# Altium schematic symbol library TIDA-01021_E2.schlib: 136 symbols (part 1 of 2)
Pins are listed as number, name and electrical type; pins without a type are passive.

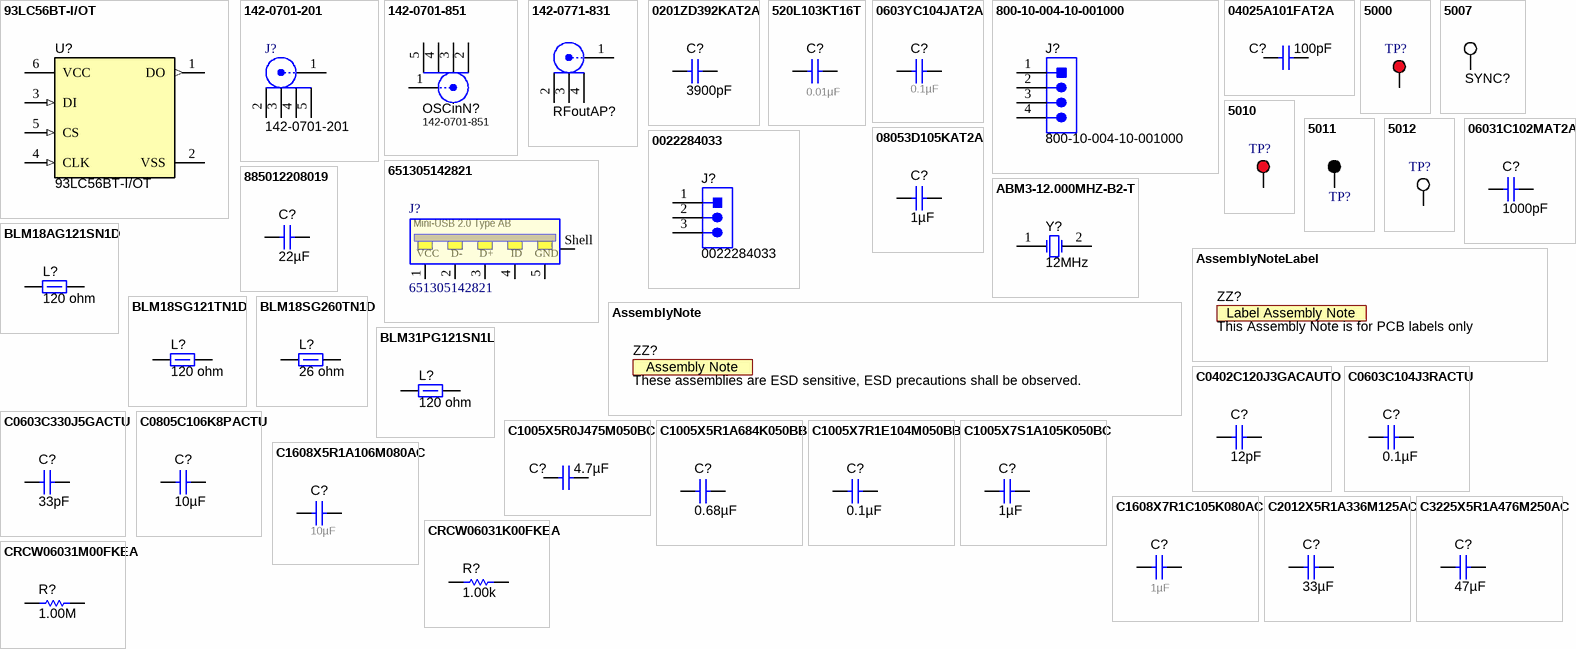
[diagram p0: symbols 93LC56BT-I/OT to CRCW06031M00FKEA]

## 93LC56BT-I/OT
designator U?
2K Microwire Compatible Serial EEPROM, SOT-23-6; Manufacturer: Microchip; SymbolCreator: x0208326; SizeAreaWB_mm2: 14.82; SizeArea_mm2: 8.12; SizeX_mm: 2.9; SizeY_mm: 2.8; SizeZ_mm: 1.15
footprint SOT-23-6
pins: 1 DO (out), 2 VSS (power), 3 DI (in), 4 CLK (in), 5 CS (in), 6 VCC (power)

## 142-0701-201
designator J?
Connector, TH, SMA; Manufacturer: Emerson Network Power; SymbolCreator: X0208326
footprint Johnson_142-0701-20x (Johnson Components recommended land pattern)
pins: 1, 2, 3, 4, 5

## 142-0701-851
designator OSCinN?
Connector, SMT, End launch SMA 50 ohm; Manufacturer: Emerson Network Power Connectivity; U/M: EA
footprint EMERSON_142-0701-851 (Johnson Components)
pins: 1, 2, 3, 4, 5

## 142-0771-831
designator RFoutAP?  (value not drawn)
JACK, SMA, 50 Ohm, Gold, Edge Mount; Manufacturer: Johnson; SymbolCreator: Altium; Gender: Female; Voltage_V: 170
footprint Johnson_142-0771-831
pins: 1, 2, 3, 4

## 0201ZD392KAT2A
designator C?  ValueDisplayed: 3900pF  (hidden comment: 0201ZD392KAT2A)
CAP, CERM, 3900 pF, 10 V, +/- 10%, X5R, 0201; Manufacturer: AVX; Polarized: N; CompType: Capacitor; Value: 3900pF; U/M: EA; Cap_F: 0.0000000039; Tolerance_%: 10; Value1: Unknown; Value2: 10V; TaMin_C: -55; TaMax_C: 85; Cap_Case: 0201; SizeArea_mm2: 0.18; SizeAreaWB_mm2: 2.08; SizeX_mm: 0.6; SizeY_mm: 0.3; SizeZ_mm: 0.26; AEC Category: Q200
signal-integrity model Cap
simulation model Cap
footprint 0201
footprint 0201M
footprint 0201L
footprint 0201_Silk
pins: 1, 2

## 520L103KT16T
designator C?  ValueDisplayed: 0.01µF  (hidden comment: 520L103KT16T)
CAP, CERM, 0.01 µF, 16 V, +/- 10%, X7R, 0402; Manufacturer: AT Ceramics; Polarized: N; CompType: Capacitor; Value: 0.01uF; U/M: EA; Cap_F: 0.00000001; Tolerance_%: 10; Value1: Unknown; VDC_V: 16; Value2: 16V; TaMin_C: -55; TaMax_C: 125; Cap_Case: 0402; AEC Category: Q200; SizeArea_mm2: 0.5; SizeAreaWB_mm2: 3; SizeX_mm: 1; SizeZ_mm: 0.65
signal-integrity model Cap
simulation model Cap
footprint 0402_065
footprint 0402_065M
footprint 0402_065L
footprint 0402_065S
pins: 1, 2

## 0603YC104JAT2A
designator C?  ValueDisplayed: 0.1µF  (hidden comment: 0603YC104JAT2A)
CAP, CERM, 0.1uF, 16V, +/-5%, X7R, 0603; Manufacturer: AVX; Cap_Case: 0603; ESR_Ohm: 0.039; Polarized: N; TaMax_C: 125; TaMin_C: -55; Tolerance_%: 5; VDC_V: 16; Cap_F: 0.0000001; CompType: Capacitor; Value1: 0.039 ohm; U/M: EA
signal-integrity model Cap
simulation model Cap
footprint 0603
footprint 0603M
footprint 0603L
footprint 0603_HV
pins: 1, 2

## 800-10-004-10-001000
designator J?
Header, 100mil, 4x1, TH; Manufacturer: Mill-Max; SymbolCreator: a0412235
footprint Mill-Max_800-10-004-10-001000
pins: 1, 2, 3, 4

## 04025A101FAT2A
designator C?  ValueDisplayed: 100pF  (hidden comment: 04025A101FAT2A)
CAP, CERM, 100 pF, 50 V, +/- 1%, C0G/NP0, 0402; Manufacturer: AVX; Polarized: N; CompType: Capacitor; Value: 100pF; U/M: EA; Cap_F: 0.0000000001; Tolerance_%: 1; Value1: Unknown; VDC_V: 50; Value2: 50V; TaMin_C: -55; TaMax_C: 125; Cap_Case: 0402; SizeArea_mm2: 0.5; SizeAreaWB_mm2: 3; SizeZ_mm: 0.6; AEC Category: Q200
signal-integrity model Cap
simulation model Cap
footprint 0402
footprint 0402M
footprint 0402L
footprint 0402S
pins: 1, 2

## 5000
designator TP?  (value not drawn)
Test Point, Miniature, Red, TH; Manufacturer: Keystone; CompType: Test Point Loop; ContactFinish: Silver
footprint Keystone5000
pins: 1

## 5007
designator SYNC?  (value not drawn)
Test Point, Compact, White, TH; Manufacturer: Keystone; CompType: Test Point Loop; U/M: EA
footprint Keystone5007
pins: 1

## 5010
designator TP?  (value not drawn)
Test Point, Multipurpose, Red, TH; Manufacturer: Keystone; CompType: Test Point Loop; ContactFinish: Silver
footprint Keystone5010
pins: 1

## 5011
designator TP?  (value not drawn)
Test Point, Multipurpose, Black, TH; Manufacturer: Keystone; CompType: Test Point Loop; ContactFinish: Silver
footprint Keystone5011
pins: 1

## 5012
designator TP?  (value not drawn)
Test Point, Multipurpose, White, TH; Manufacturer: Keystone; CompType: Test Point Loop; ContactFinish: Silver
footprint Keystone5012
pins: 1

## 06031C102MAT2A
designator C?  ValueDisplayed: 1000pF  (hidden comment: 06031C102MAT2A)
CAP, CERM, 1000 pF, 100 V, +/- 20%, X7R, 0603; Manufacturer: AVX; Polarized: N; CompType: Capacitor; Value: 1000pF; U/M: EA; Cap_F: 0.000000001; Tolerance_%: 20; ESR_ohm: 0.276; Value1: 0.276 ohm; VDC_V: 100; Value2: 100V; TaMin_C: -55; TaMax_C: 125; Cap_Case: 0603; SizeArea_mm2: 1.28; SizeAreaWB_mm2: 4.68; SizeX_mm: 1.6; SizeY_mm: 0.8; SizeZ_mm: 1; AEC Category: Q200
signal-integrity model Cap
simulation model Cap
footprint 0603
footprint 0603M
footprint 0603L
footprint 0603_HV
footprint 0603S
pins: 1, 2

## 08053D105KAT2A
designator C?  ValueDisplayed: 1µF  (hidden comment: 08053D105KAT2A)
CAP, CERM, 1 µF, 25 V, +/- 10%, X5R, 0805; Manufacturer: AVX; Polarized: N; CompType: Capacitor; Value: 1uF; U/M: EA; Cap_F: 0.000001; Tolerance_%: 10; ESR_ohm: 0.012; Value1: 0.012 ohm; VDC_V: 25; Value2: 25V; TaMin_C: -55; TaMax_C: 85; Cap_Case: 0805; SizeArea_mm2: 2.5; SizeAreaWB_mm2: 6.75; SizeX_mm: 2; SizeY_mm: 1.25; SizeZ_mm: 1.45; AEC Category: Q200
signal-integrity model Cap
simulation model Cap
footprint 0805_HV
footprint 0805_HV1
footprint 0805
footprint 0805M
footprint 0805L
pins: 1, 2

## 0022284033
designator J?
Header, 2.54mm, 3x1, Tin, TH; Manufacturer: Molex; SymbolCreator: a0799628; Pitch_mm: 2.54; Gender: Male; Shrouded: N; Row_Count: 1; Current_A: 4; Voltage_V: 250; Cert_UL: Y
footprint Molex_0022284033
pins: 1, 2, 3
3 alternate drawings of the same symbol

## 651305142821
designator J?
WR-COM Mini USB 2.0 Type AB SMT Horizontal 5 Contacts
footprint 651305142821 (5 pins)
pins: 1 VCC, 2 D-, 3 D+, 4 ID, 5 GND, Shell

## 885012208019
designator C?  ValueDisplayed: 22µF  (hidden comment: 885012208019)
CAP, CERM, 22 µF, 10 V, +/- 10%, X7R, 1206_190; Manufacturer: Wurth Elektronik; Polarized: N; CompType: Capacitor; Value: 22uF; U/M: EA; Cap_F: 0.000022; Tolerance_%: 10; Value1: Unknown; Value2: 10V; TaMin_C: -55; TaMax_C: 125; Cap_Case: 1206; SizeArea_mm2: 5.12; SizeAreaWB_mm2: 10.92; SizeX_mm: 3.2; SizeY_mm: 1.6; SizeZ_mm: 1.9; AEC Category: Q200
signal-integrity model Cap
simulation model Cap
footprint 1206_190
footprint 1206_190M
footprint 1206_190L
pins: 1, 2

## ABM3-12.000MHZ-B2-T
designator Y?  Frequency: 12MHz  (hidden comment: ABM3-12.000MHZ-B2-T)
Crystal, 12Mhz, 18pF, SMD; Manufacturer: Abracon Corporation; SymbolCreator: a0412235; U/M: EA; TaMin_C: -20; TaMax_C: 70; Frequency Stability: ±50ppm
footprint XTAL_ABM3
pins: 1 OSC1, 2 OSC2

## AssemblyNote
designator ZZ?, comment These assemblies are ESD sensitive, ESD precautions shall be observed.  (no BOM)
SymbolCreator: codlsc; CompType: AssemblyNote
footprint AssemblyNote

## AssemblyNoteLabel
designator ZZ?, comment This Assembly Note is for PCB labels only  (no BOM)
SymbolCreator: a0412235
footprint AssemblyNoteLabel

## BLM18AG121SN1D
designator L?  ValueDisplayed: 120 ohm  (hidden comment: BLM18AG121SN1D)
Ferrite Bead, 120 ohm @ 100 MHz, 0.5 A, 0603; Manufacturer: MuRata; Value: 120 ohm; Imax_A: 0.5; DCR_ohm: 0.18; Value1: 0.18 ohm; Value2: 0.5A; SizeAreaWB_mm2: 4.68; SizeArea_mm2: 1.28; SizeX_mm: 1.6; SizeY_mm: 0.8; SizeZ_mm: 1; ZTyp@100MHz_Ohm: 120
footprint 0603
footprint 0603M
footprint 0603L
footprint 0603_HV
footprint 0603S
pins: 1, 2

## BLM18SG121TN1D
designator L?  ValueDisplayed: 120 ohm  (hidden comment: BLM18SG121TN1D)
Ferrite Bead, 120 ohm @ 100 MHz, 3 A, 0603; Manufacturer: MuRata; Value: 120 ohm; Imax_A: 3; DCR_ohm: 0.025; Value1: 0.025 ohm; Value2: 3A; SizeAreaWB_mm2: 4.68; SizeArea_mm2: 1.28; SizeX_mm: 1.6; SizeY_mm: 0.8; SizeZ_mm: 1; ZTyp@100MHz_Ohm: 120
footprint 0603
footprint 0603M
footprint 0603L
footprint 0603_HV
footprint 0603S
pins: 1, 2

## BLM18SG260TN1D
designator L?  ValueDisplayed: 26 ohm  (hidden comment: BLM18SG260TN1D)
Ferrite Bead, 26 ohm @ 100 MHz, 6 A, 0603; Manufacturer: MuRata; Value: 26 ohm; Imax_A: 6; DCR_ohm: 0.007; Value1: 0.007 ohm; Value2: 6A; SizeAreaWB_mm2: 4.68; SizeArea_mm2: 1.28; SizeX_mm: 1.6; SizeY_mm: 0.8; SizeZ_mm: 1; ZTyp@100MHz_Ohm: 26
footprint 0603
footprint 0603M
footprint 0603L
footprint 0603_HV
footprint 0603S
pins: 1, 2

## BLM31PG121SN1L
designator L?  ValueDisplayed: 120 ohm  (hidden comment: BLM31PG121SN1L)
Ferrite Bead, 120 ohm @ 100 MHz, 3.5 A, 1206; Manufacturer: MuRata; Value: 120 ohm; Imax_A: 3.5; DCR_ohm: 0.02; Value1: 0.02 ohm; Value2: 3.5A; SizeAreaWB_mm2: 10.92; SizeArea_mm2: 5.12; SizeX_mm: 3.2; SizeY_mm: 1.6; SizeZ_mm: 1.35; ZTyp@100MHz_Ohm: 120
footprint 1206
footprint 1206M
footprint 1206L
pins: 1, 2

## C0402C120J3GACAUTO
designator C?  ValueDisplayed: 12pF  (hidden comment: C0402C120J3GACAUTO)
CAP, CERM, 12 pF, 25 V, +/- 5%, C0G/NP0, AEC-Q200 Grade 1, 0402; Manufacturer: Kemet; Polarized: N; CompType: Capacitor; Value: 12pF; U/M: EA; Cap_F: 0.000000000012; Tolerance_%: 5; Value1: Unknown; VDC_V: 25; Value2: 25V; TaMin_C: -55; TaMax_C: 125; Cap_Case: 0402; SizeArea_mm2: 0.5; SizeAreaWB_mm2: 3; SizeX_mm: 1; SizeZ_mm: 0.6; AEC Category: Q200; AEC Qualified: Y
signal-integrity model Cap
simulation model Cap
footprint 0402
footprint 0402M
footprint 0402L
footprint 0402S
pins: 1, 2

## C0603C104J3RACTU
designator C?  ValueDisplayed: 0.1µF  (hidden comment: C0603C104J3RACTU)
CAP, CERM, 0.1uF, 25V, +/-5%, X7R, 0603; Manufacturer: Kemet; Cap_Case: 0603; Polarized: N; TaMax_C: 125; TaMin_C: -55; Tolerance_%: 5; VDC_V: 25; Cap_F: 0.0000001; CompType: Capacitor; Value1: Unknown; U/M: EA
signal-integrity model Cap
simulation model Cap
footprint 0603
footprint 0603M
footprint 0603L
footprint 0603_HV
pins: 1, 2

## C0603C330J5GACTU
designator C?  ValueDisplayed: 33pF  (hidden comment: C0603C330J5GACTU)
CAP, CERM, 33pF, 50V, +/-5%, C0G/NP0, 0603; Manufacturer: Kemet; Cap_Case: 0603; Polarized: N; TaMax_C: 125; TaMin_C: -55; Tolerance_%: 5; VDC_V: 50; Cap_F: 0.000000000033; CompType: Capacitor; U/M: EA; Value1: Unknown
signal-integrity model Cap
simulation model Cap
footprint 0603
footprint 0603M
footprint 0603L
footprint 0603_HV
pins: 1, 2

## C0805C106K8PACTU
designator C?  ValueDisplayed: 10µF  (hidden comment: C0805C106K8PACTU)
CAP, CERM, 10uF, 10V, +/-10%, X5R, 0805; Manufacturer: Kemet; Cap_Case: 0805; ESR_Ohm: 0.003; IRMS_A: 11.43; Polarized: N; TaMax_C: 85; TaMin_C: -55; Tolerance_%: 10; Cap_F: 0.00001; CompType: Capacitor; Value1: 0.003 ohm; U/M: EA
signal-integrity model Cap
simulation model Cap
footprint 0805_HV
footprint 0805
footprint 0805M
footprint 0805L
pins: 1, 2

## C1005X5R0J475M050BC
designator C?  ValueDisplayed: 4.7µF  (hidden comment: C1005X5R0J475M050BC)
CAP, CERM, 4.7 µF, 6.3 V, +/- 20%, X5R, 0402; Manufacturer: TDK; Polarized: N; CompType: Capacitor; Value: 4.7uF; U/M: EA; Cap_F: 0.0000047; Tolerance_%: 20; Value1: Unknown; VDC_V: 6.3; Value2: 6.3V; TaMin_C: -55; TaMax_C: 85; Cap_Case: 0402; SizeArea_mm2: 0.5; SizeAreaWB_mm2: 3; SizeX_mm: 1; SizeZ_mm: 0.6; AEC Category: Q200
signal-integrity model Cap
simulation model Cap
footprint 0402
footprint 0402M
footprint 0402L
footprint 0402S
pins: 1, 2

## C1005X5R1A684K050BB
designator C?  ValueDisplayed: 0.68µF  (hidden comment: C1005X5R1A684K050BB)
CAP, CERM, 0.68 µF, 10 V, +/- 10%, X5R, 0402; Manufacturer: TDK; Polarized: N; CompType: Capacitor; Value: 0.68uF; U/M: EA; Cap_F: 0.00000068; Tolerance_%: 10; Value1: Unknown; Value2: 10V; TaMin_C: -55; TaMax_C: 85; Cap_Case: 0402; SizeArea_mm2: 0.5; SizeAreaWB_mm2: 3; SizeX_mm: 1; SizeZ_mm: 0.6; AEC Category: Q200
signal-integrity model Cap
simulation model Cap
footprint 0402
footprint 0402M
footprint 0402L
footprint 0402S
pins: 1, 2

## C1005X7R1E104M050BB
designator C?  ValueDisplayed: 0.1µF  (hidden comment: C1005X7R1E104M050BB)
CAP, CERM, 0.1 µF, 25 V, +/- 20%, X7R, 0402; Manufacturer: TDK; Cap_Case: 0402; Polarized: N; TaMax_C: 125; TaMin_C: -55; Tolerance_%: 20; VDC_V: 25; Cap_F: 0.0000001; CompType: Capacitor; Value: 0.1uF; Value1: Unknown; Value2: 25V; U/M: EA; SizeArea_mm2: 0.5; SizeAreaWB_mm2: 3; SizeX_mm: 1; SizeZ_mm: 0.6; AEC Category: Q200
signal-integrity model Cap
simulation model Cap
footprint 0402
footprint 0402M
footprint 0402L
footprint 0402S
pins: 1, 2

## C1005X7S1A105K050BC
designator C?  ValueDisplayed: 1µF  (hidden comment: C1005X7S1A105K050BC)
CAP, CERM, 1 µF, 10 V, +/- 10%, X7S, 0402; Manufacturer: TDK; Polarized: N; CompType: Capacitor; Value: 1uF; U/M: EA; Cap_F: 0.000001; Tolerance_%: 10; ESR_ohm: 0.011416; Value1: 0.011416 ohm; Value2: 10V; IRMS_A: 1.483; TaMin_C: -55; TaMax_C: 125; Cap_Case: 0402; SizeArea_mm2: 0.5; SizeAreaWB_mm2: 3; SizeX_mm: 1; SizeZ_mm: 0.6; AEC Category: Q200
signal-integrity model Cap
simulation model Cap
footprint 0402
footprint 0402M
footprint 0402L
footprint 0402S
pins: 1, 2

## C1608X5R1A106M080AC
designator C?  ValueDisplayed: 10µF  (hidden comment: C1608X5R1A106M080AC)
CAP, CERM, 10 µF, 10 V, +/- 20%, X5R, 0603; Manufacturer: TDK; Cap_Case: 0603; ESR_ohm: 0.0078; IRMS_A: 1.85; Polarized: N; TaMax_C: 85; TaMin_C: -55; Tolerance_%: 20; VDC_V: 10; Cap_F: 0.00001; CompType: Capacitor; Value: 10uF; U/M: EA; Value1: 0.0078 ohm; Value2: 10V; AEC Category: Q200
signal-integrity model Cap
simulation model Cap
footprint 0603
footprint 0603M
footprint 0603L
footprint 0603_HV
footprint 0603S
pins: 1, 2

## C1608X7R1C105K080AC
designator C?  ValueDisplayed: 1µF  (hidden comment: C1608X7R1C105K080AC)
CAP, CERM, 1 µF, 16 V, +/- 10%, X7R, 0603; Manufacturer: TDK; Cap_Case: 0603; ESR_ohm: 0.0057; Polarized: N; TaMax_C: 125; TaMin_C: -55; Tolerance_%: 10; VDC_V: 16; Cap_F: 0.000001; CompType: Capacitor; Value: 1uF; Value1: 0.0057 ohm; Value2: 16V; U/M: EA; SizeArea_mm2: 1.28; SizeAreaWB_mm2: 4.68; SizeX_mm: 1.6; SizeY_mm: 0.8; SizeZ_mm: 1; AEC Category: Q200
signal-integrity model Cap
simulation model Cap
footprint 0603
footprint 0603M
footprint 0603L
footprint 0603_HV
footprint 0603S
pins: 1, 2

## C2012X5R1A336M125AC
designator C?  ValueDisplayed: 33µF  (hidden comment: C2012X5R1A336M125AC)
CAP, CERM, 33 µF, 10 V, +/- 20%, X5R, 0805; Manufacturer: TDK; Polarized: N; CompType: Capacitor; Value: 33uF; U/M: EA; Cap_F: 0.000033; Tolerance_%: 20; ESR_ohm: 0.001694; Value1: 0.001694 ohm; VDC_V: 10; Value2: 10V; IRMS_A: 5.01281; TaMin_C: -55; TaMax_C: 85; Cap_Case: 0805; SizeArea_mm2: 2.5; SizeAreaWB_mm2: 6.75; SizeX_mm: 2; SizeY_mm: 1.25; SizeZ_mm: 1.45; AEC Category: Q200
signal-integrity model Cap
simulation model Cap
footprint 0805_HV
footprint 0805_HV1
footprint 0805
footprint 0805M
footprint 0805L
pins: 1, 2

## C3225X5R1A476M250AC
designator C?  ValueDisplayed: 47µF  (hidden comment: C3225X5R1A476M250AC)
CAP, CERM, 47 µF, 10 V, +/- 20%, X5R, 1210; Manufacturer: TDK; Polarized: N; CompType: Capacitor; Value: 47uF; U/M: EA; Cap_F: 0.000047; Tolerance_%: 20; ESR_ohm: 0.003602; Value1: 0.003602 ohm; VDC_V: 10; Value2: 10V; IRMS_A: 3.87414; TaMin_C: -55; TaMax_C: 85; Cap_Case: 1210_280; SizeArea_mm2: 8; SizeAreaWB_mm2: 14.7; SizeX_mm: 3.2; SizeY_mm: 2.5; SizeZ_mm: 2.8; AEC Category: Q200
signal-integrity model Cap
simulation model Cap
footprint 1210_280
pins: 1, 2

## CRCW06031K00FKEA
designator R?  ValueDisplayed: 1.00k  (hidden comment: CRCW06031K00FKEA)
RES, 1.00 k, 1%, 0.1 W, 0603; Manufacturer: Vishay-Dale; CompType: Resistor; Value: 1.00k; Res_ohm: 1000; Value_Code: 1k00; Tolerance_%: 1; Power_W: 0.1; Value2: 0.1W; VDC_V: 75; TempCo: 100 ppm/C; SizeArea_mm2: 1.28; SizeX_mm: 1.6; SizeY_mm: 0.8; EIA_Code: E96; U/M: EA; AEC Category: Q200
signal-integrity model Resistor
simulation model Resistor
footprint 0603
footprint 0603M
footprint 0603L
footprint 0603_HV
footprint 0603S
pins: 1, 2

## CRCW06031M00FKEA
designator R?  ValueDisplayed: 1.00M  (hidden comment: CRCW06031M00FKEA)
RES, 1.00 M, 1%, 0.1 W, 0603; Manufacturer: Vishay-Dale; CompType: Resistor; Value: 1.00Meg; Res_ohm: 1000000; Value_Code: 1M00; Tolerance_%: 1; Power_W: 0.1; Value2: 0.1W; VDC_V: 75; TempCo: 100 ppm/C; SizeArea_mm2: 1.28; SizeX_mm: 1.6; SizeY_mm: 0.8; EIA_Code: E96; U/M: EA; AEC Category: Q200
signal-integrity model Resistor
simulation model Resistor
footprint 0603
footprint 0603M
footprint 0603L
footprint 0603_HV
footprint 0603S
pins: 1, 2

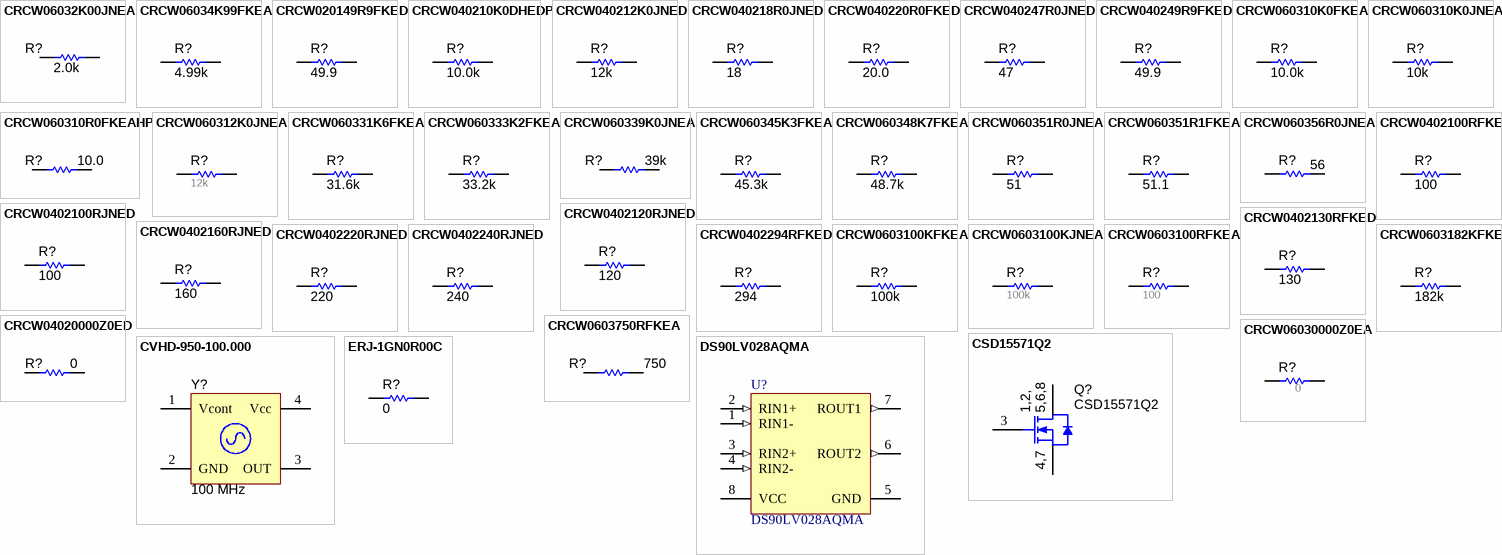
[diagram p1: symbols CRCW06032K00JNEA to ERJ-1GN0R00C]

## CRCW06032K00JNEA
designator R?  ValueDisplayed: 2.0k  (hidden comment: CRCW06032K00JNEA)
RES, 2.0 k, 5%, 0.1 W, 0603; Manufacturer: Vishay-Dale; CompType: Resistor; Value: 2.0k; Res_ohm: 2000; Value_Code: 2k00; Tolerance_%: 5; Power_W: 0.1; Value2: 0.1W; VDC_V: 75; TempCo: 200 ppm/C; SizeArea_mm2: 1.28; SizeX_mm: 1.6; SizeY_mm: 0.8; SizeZ_mm: 1; EIA_Code: E24; U/M: EA; AEC Category: Q200
signal-integrity model Resistor
simulation model Resistor
footprint 0603
footprint 0603M
footprint 0603L
footprint 0603_HV
footprint 0603S
pins: 1, 2

## CRCW06034K99FKEA
designator R?  ValueDisplayed: 4.99k  (hidden comment: CRCW06034K99FKEA)
RES, 4.99 k, 1%, 0.1 W, 0603; Manufacturer: Vishay-Dale; CompType: Resistor; Value: 4.99k; Res_ohm: 4990; Value_Code: 4k99; Tolerance_%: 1; Power_W: 0.1; Value2: 0.1W; VDC_V: 75; TempCo: 100 ppm/C; SizeArea_mm2: 1.28; SizeX_mm: 1.6; SizeY_mm: 0.8; EIA_Code: E96; U/M: EA; AEC Category: Q200
signal-integrity model Resistor
simulation model Resistor
footprint 0603
footprint 0603M
footprint 0603L
footprint 0603_HV
footprint 0603S
pins: 1, 2

## CRCW020149R9FKED
designator R?  ValueDisplayed: 49.9  (hidden comment: CRCW020149R9FKED)
RES, 49.9, 1%, 0.05 W, 0201; Manufacturer: Vishay-Dale; CompType: Resistor; Value: 49.9; Value_Code: 49R9; Tolerance_%: 1; Power_W: 0.05; Value2: 0.05W; VDC_V: 30; TempCo: 100 ppm/C; SizeArea_mm2: 0.18; SizeX_mm: 0.6; SizeY_mm: 0.3; SizeZ_mm: 0.26; EIA_Code: E96; U/M: EA; AEC Category: Q200; AEC Qualified: N
signal-integrity model Resistor
simulation model Resistor
footprint 0201
footprint 0201M
footprint 0201L
footprint 0201_Silk
pins: 1, 2

## CRCW040210K0DHEDP
designator R?  ValueDisplayed: 10.0k  (hidden comment: CRCW040210K0DHEDP)
RES, 10.0 k, 0.5%, 0.063 W, 0402; Manufacturer: Vishay-Dale; CompType: Resistor; Value: 10.0k; Res_ohm: 10000; Value_Code: 10k0; Tolerance_%: 0.5; Power_W: 0.063; Value2: 0.063W; VDC_V: 50; TempCo: 50 ppm/C; SizeX_mm: 1; SizeZ_mm: 0.6; EIA_Code: E192; U/M: EA; AEC Category: Q200
signal-integrity model Resistor
simulation model Resistor
footprint 0402
footprint 0402M
footprint 0402L
footprint 0402S
pins: 1, 2

## CRCW040212K0JNED
designator R?  ValueDisplayed: 12k  (hidden comment: CRCW040212K0JNED)
RES, 12 k, 5%, 0.063 W, 0402; Manufacturer: Vishay-Dale; CompType: Resistor; Value: 12k; Res_ohm: 12000; Value_Code: 12k0; Tolerance_%: 5; Power_W: 0.063; Value2: 0.063W; VDC_V: 50; TempCo: 200 ppm/C; EIA_Code: E24; U/M: EA; AEC Category: Q200
signal-integrity model Resistor
simulation model Resistor
footprint 0402
footprint 0402M
footprint 0402L
footprint 0402S
pins: 1, 2

## CRCW040218R0JNED
designator R?  ValueDisplayed: 18  (hidden comment: CRCW040218R0JNED)
RES, 18, 5%, 0.063 W, 0402; Manufacturer: Vishay-Dale; CompType: Resistor; Value: 18; Value_Code: 18R0; Tolerance_%: 5; Power_W: 0.063; Value2: 0.063W; VDC_V: 50; TempCo: 200 ppm/C; EIA_Code: E24; U/M: EA; AEC Category: Q200
signal-integrity model Resistor
simulation model Resistor
footprint 0402
footprint 0402M
footprint 0402L
footprint 0402S
pins: 1, 2

## CRCW040220R0FKED
designator R?  ValueDisplayed: 20.0  (hidden comment: CRCW040220R0FKED)
RES, 20.0, 1%, 0.063 W, 0402; Manufacturer: Vishay-Dale; CompType: Resistor; Value: 20.0; Res_ohm: 20; Value_Code: 20R0; Tolerance_%: 1; Power_W: 0.063; Value2: 0.063W; VDC_V: 50; TempCo: 100 ppm/C; SizeArea_mm2: 0.5; SizeZ_mm: 0.6; EIA_Code: E96; U/M: EA; AEC Category: Q200
signal-integrity model Resistor
simulation model Resistor
footprint 0402
footprint 0402M
footprint 0402L
footprint 0402S
pins: 1, 2

## CRCW040247R0JNED
designator R?  ValueDisplayed: 47  (hidden comment: CRCW040247R0JNED)
RES, 47, 5%, 0.063 W, 0402; Manufacturer: Vishay-Dale; CompType: Resistor; Value: 47; Value_Code: 47R0; Tolerance_%: 5; Power_W: 0.063; Value2: 0.063W; VDC_V: 50; TempCo: 200 ppm/C; SizeArea_mm2: 0.5; SizeX_mm: 1; SizeZ_mm: 0.6; EIA_Code: E24; U/M: EA; AEC Category: Q200
signal-integrity model Resistor
simulation model Resistor
footprint 0402
footprint 0402M
footprint 0402L
footprint 0402S
pins: 1, 2

## CRCW040249R9FKED
designator R?  ValueDisplayed: 49.9  (hidden comment: CRCW040249R9FKED)
RES, 49.9, 1%, 0.063 W, 0402; Manufacturer: Vishay-Dale; CompType: Resistor; Value: 49.9; Value_Code: 49R9; Tolerance_%: 1; Power_W: 0.063; Value2: 0.063W; VDC_V: 50; TempCo: 100 ppm/C; EIA_Code: E96; U/M: EA; AEC Category: Q200
signal-integrity model Resistor
simulation model Resistor
footprint 0402
footprint 0402M
footprint 0402L
footprint 0402S
pins: 1, 2

## CRCW060310K0FKEA
designator R?  ValueDisplayed: 10.0k  (hidden comment: CRCW060310K0FKEA)
RES, 10.0 k, 1%, 0.1 W, 0603; Manufacturer: Vishay-Dale; CompType: Resistor; Value: 10.0k; Res_ohm: 10000; Value_Code: 10k0; Tolerance_%: 1; Power_W: 0.1; Value2: 0.1W; VDC_V: 75; TempCo: 100 ppm/C; SizeArea_mm2: 1.28; SizeX_mm: 1.6; SizeY_mm: 0.8; EIA_Code: E96; U/M: EA; AEC Category: Q200
signal-integrity model Resistor
simulation model Resistor
footprint 0603
footprint 0603M
footprint 0603L
footprint 0603_HV
footprint 0603S
pins: 1, 2

## CRCW060310K0JNEA
designator R?  ValueDisplayed: 10k  (hidden comment: CRCW060310K0JNEA)
RES, 10 k, 5%, 0.1 W, 0603; Manufacturer: Vishay-Dale; CompType: Resistor; Value: 10k; Res_ohm: 10000; Value_Code: 10k0; Tolerance_%: 5; Power_W: 0.1; Value2: 0.1W; VDC_V: 75; TempCo: 200 ppm/C; SizeArea_mm2: 1.28; SizeX_mm: 1.6; SizeY_mm: 0.8; SizeZ_mm: 1; EIA_Code: E24; U/M: EA; AEC Category: Q200
signal-integrity model Resistor
simulation model Resistor
footprint 0603
footprint 0603M
footprint 0603L
footprint 0603_HV
footprint 0603S
pins: 1, 2

## CRCW060310R0FKEAHP
designator R?  ValueDisplayed: 10.0  (hidden comment: CRCW060310R0FKEAHP)
RES, 10.0, 1%, 0.25 W, 0603; Manufacturer: Vishay-Dale; CompType: Resistor; Value: 10.0; Res_ohm: 10; Value_Code: 10R0; Tolerance_%: 1; Power_W: 0.25; Value2: 0.25W; VDC_V: 75; TempCo: 100 ppm/C; SizeArea_mm2: 1.28; SizeX_mm: 1.6; SizeY_mm: 0.8; EIA_Code: E96; U/M: EA; AEC Category: Q200
signal-integrity model Resistor
simulation model Resistor
footprint 0603
footprint 0603M
footprint 0603L
footprint 0603_HV
footprint 0603S
pins: 1, 2

## CRCW060312K0JNEA
designator R?  value 12k  (hidden comment: CRCW060312K0JNEA)
RES, 12k ohm, 5%, 0.1W, 0603; Manufacturer: Vishay-Dale; CompType: Resistor; Tolerance_%: 5; VDC_V: 75; Power_W: 0.1; Res_ohm: 12000; U/M: EA; Value_Code: 12k0; EIA_Code: E24
signal-integrity model Resistor
simulation model Resistor
footprint 0603
footprint 0603M
footprint 0603L
footprint 0603_HV
pins: 1, 2

## CRCW060331K6FKEA
designator R?  ValueDisplayed: 31.6k  (hidden comment: CRCW060331K6FKEA)
RES, 31.6 k, 1%, 0.1 W, 0603; Manufacturer: Vishay-Dale; CompType: Resistor; Value: 31.6k; Res_ohm: 31600; Value_Code: 31k6; Tolerance_%: 1; Power_W: 0.1; Value2: 0.1W; VDC_V: 75; TempCo: 100 ppm/C; SizeArea_mm2: 1.28; SizeX_mm: 1.6; SizeY_mm: 0.8; EIA_Code: E96; U/M: EA; AEC Category: Q200
signal-integrity model Resistor
simulation model Resistor
footprint 0603
footprint 0603M
footprint 0603L
footprint 0603_HV
footprint 0603S
pins: 1, 2

## CRCW060333K2FKEA
designator R?  ValueDisplayed: 33.2k  (hidden comment: CRCW060333K2FKEA)
RES, 33.2 k, 1%, 0.1 W, 0603; Manufacturer: Vishay-Dale; CompType: Resistor; Value: 33.2k; Res_ohm: 33200; Value_Code: 33k2; Tolerance_%: 1; Power_W: 0.1; Value2: 0.1W; VDC_V: 75; TempCo: 100 ppm/C; SizeArea_mm2: 1.28; SizeX_mm: 1.6; SizeY_mm: 0.8; EIA_Code: E96; U/M: EA; AEC Category: Q200
signal-integrity model Resistor
simulation model Resistor
footprint 0603
footprint 0603M
footprint 0603L
footprint 0603_HV
footprint 0603S
pins: 1, 2

## CRCW060339K0JNEA
designator R?  ValueDisplayed: 39k  (hidden comment: CRCW060339K0JNEA)
RES, 39 k, 5%, 0.1 W, 0603; Manufacturer: Vishay-Dale; CompType: Resistor; Value: 39k; Res_ohm: 39000; Value_Code: 39k0; Tolerance_%: 5; Power_W: 0.1; Value2: 0.1W; VDC_V: 75; TempCo: 200 ppm/C; SizeArea_mm2: 1.28; SizeX_mm: 1.6; SizeY_mm: 0.8; SizeZ_mm: 1; EIA_Code: E24; U/M: EA; AEC Category: Q200
signal-integrity model Resistor
simulation model Resistor
footprint 0603
footprint 0603M
footprint 0603L
footprint 0603_HV
footprint 0603S
pins: 1, 2

## CRCW060345K3FKEA
designator R?  ValueDisplayed: 45.3k  (hidden comment: CRCW060345K3FKEA)
RES, 45.3 k, 1%, 0.1 W, 0603; Manufacturer: Vishay-Dale; CompType: Resistor; Value: 45.3k; Res_ohm: 45300; Value_Code: 45k3; Tolerance_%: 1; Power_W: 0.1; Value2: 0.1W; VDC_V: 75; TempCo: 100 ppm/C; SizeArea_mm2: 1.28; SizeX_mm: 1.6; SizeY_mm: 0.8; EIA_Code: E96; U/M: EA; AEC Category: Q200
signal-integrity model Resistor
simulation model Resistor
footprint 0603
footprint 0603M
footprint 0603L
footprint 0603_HV
footprint 0603S
pins: 1, 2

## CRCW060348K7FKEA
designator R?  ValueDisplayed: 48.7k  (hidden comment: CRCW060348K7FKEA)
RES, 48.7 k, 1%, 0.1 W, 0603; Manufacturer: Vishay-Dale; CompType: Resistor; Value: 48.7k; Res_ohm: 48700; Value_Code: 48k7; Tolerance_%: 1; Power_W: 0.1; Value2: 0.1W; VDC_V: 75; TempCo: 100 ppm/C; SizeArea_mm2: 1.28; SizeX_mm: 1.6; SizeY_mm: 0.8; EIA_Code: E96; U/M: EA; AEC Category: Q200
signal-integrity model Resistor
simulation model Resistor
footprint 0603
footprint 0603M
footprint 0603L
footprint 0603_HV
footprint 0603S
pins: 1, 2

## CRCW060351R0JNEA
designator R?  value 51  (hidden comment: CRCW060351R0JNEA)
RES, 51 ohm, 5%, 0.1W, 0603; Manufacturer: Vishay-Dale; CompType: Resistor; Tolerance_%: 5; VDC_V: 75; Power_W: 0.1; Value_Code: 51R0; EIA_Code: E24; TempCo: 200 ppm/C; U/M: EA
signal-integrity model Resistor
simulation model Resistor
footprint 0603
footprint 0603M
footprint 0603L
footprint 0603_HV
pins: 1, 2

## CRCW060351R1FKEA
designator R?  ValueDisplayed: 51.1  (hidden comment: CRCW060351R1FKEA)
RES, 51.1, 1%, 0.1 W, 0603; Manufacturer: Vishay-Dale; CompType: Resistor; Value: 51.1; Value_Code: 51R1; Tolerance_%: 1; Power_W: 0.1; Value2: 0.1W; VDC_V: 75; TempCo: 100 ppm/C; SizeArea_mm2: 1.28; SizeX_mm: 1.6; SizeY_mm: 0.8; EIA_Code: E96; U/M: EA; AEC Category: Q200
signal-integrity model Resistor
simulation model Resistor
footprint 0603
footprint 0603M
footprint 0603L
footprint 0603_HV
footprint 0603S
pins: 1, 2

## CRCW060356R0JNEA
designator R?  ValueDisplayed: 56  (hidden comment: CRCW060356R0JNEA)
RES, 56, 5%, 0.1 W, 0603; Manufacturer: Vishay-Dale; CompType: Resistor; Tolerance_%: 5; VDC_V: 75; Power_W: 0.1; Value: 56; U/M: EA; Value_Code: 56R0; Value2: 0.1W; EIA_Code: E24; TempCo: 200 ppm/C; SizeArea_mm2: 1.28; SizeX_mm: 1.6; SizeY_mm: 0.8; SizeZ_mm: 1; AEC Category: Q200
signal-integrity model Resistor
simulation model Resistor
footprint 0603
footprint 0603M
footprint 0603L
footprint 0603_HV
footprint 0603S
pins: 1, 2

## CRCW0402100RFKED
designator R?  ValueDisplayed: 100  (hidden comment: CRCW0402100RFKED)
RES, 100, 1%, 0.063 W, 0402; Manufacturer: Vishay-Dale; CompType: Resistor; Value: 100; Value_Code: 100R; Tolerance_%: 1; Power_W: 0.063; Value2: 0.063W; VDC_V: 50; TempCo: 100 ppm/C; EIA_Code: E96; U/M: EA; AEC Category: Q200; SizeArea_mm2: 0.5; SizeZ_mm: 0.6
signal-integrity model Resistor
simulation model Resistor
footprint 0402
footprint 0402M
footprint 0402L
footprint 0402S
pins: 1, 2

## CRCW0402100RJNED
designator R?  ValueDisplayed: 100  (hidden comment: CRCW0402100RJNED)
RES, 100, 5%, 0.063 W, 0402; Manufacturer: Vishay-Dale; CompType: Resistor; Value: 100; Value_Code: 100R; Tolerance_%: 5; Power_W: 0.063; Value2: 0.063W; VDC_V: 50; TempCo: 200 ppm/C; SizeArea_mm2: 0.5; SizeX_mm: 1; SizeZ_mm: 0.6; EIA_Code: E24; U/M: EA; AEC Category: Q200
signal-integrity model Resistor
simulation model Resistor
footprint 0402
footprint 0402M
footprint 0402L
footprint 0402S
pins: 1, 2

## CRCW0402120RJNED
designator R?  ValueDisplayed: 120  (hidden comment: CRCW0402120RJNED)
RES, 120, 5%, 0.063 W, 0402; Manufacturer: Vishay-Dale; CompType: Resistor; Value: 120; Value_Code: 120R; Tolerance_%: 5; Power_W: 0.063; Value2: 0.063W; VDC_V: 50; TempCo: 200 ppm/C; SizeArea_mm2: 0.5; SizeX_mm: 1; SizeZ_mm: 0.6; EIA_Code: E24; U/M: EA; AEC Category: Q200
signal-integrity model Resistor
simulation model Resistor
footprint 0402
footprint 0402M
footprint 0402L
footprint 0402S
pins: 1, 2

## CRCW0402130RFKED
designator R?  ValueDisplayed: 130  (hidden comment: CRCW0402130RFKED)
RES, 130, 1%, 0.063 W, 0402; Manufacturer: Vishay-Dale; CompType: Resistor; Value: 130; Value_Code: 130R; Tolerance_%: 1; Power_W: 0.063; Value2: 0.063W; VDC_V: 50; TempCo: 100 ppm/C; SizeArea_mm2: 0.5; SizeZ_mm: 0.6; EIA_Code: E96; U/M: EA; AEC Category: Q200
signal-integrity model Resistor
simulation model Resistor
footprint 0402
footprint 0402M
footprint 0402L
footprint 0402S
pins: 1, 2

## CRCW0402160RJNED
designator R?  ValueDisplayed: 160  (hidden comment: CRCW0402160RJNED)
RES, 160, 5%, 0.063 W, 0402; Manufacturer: Vishay-Dale; CompType: Resistor; Value: 160; Value_Code: 160R; Tolerance_%: 5; Power_W: 0.063; Value2: 0.063W; VDC_V: 50; TempCo: 200 ppm/C; SizeArea_mm2: 0.5; SizeX_mm: 1; SizeZ_mm: 0.6; EIA_Code: E24; U/M: EA; AEC Category: Q200
signal-integrity model Resistor
simulation model Resistor
footprint 0402
footprint 0402M
footprint 0402L
footprint 0402S
pins: 1, 2

## CRCW0402220RJNED
designator R?  ValueDisplayed: 220  (hidden comment: CRCW0402220RJNED)
RES, 220, 5%, 0.063 W, 0402; Manufacturer: Vishay-Dale; CompType: Resistor; Value: 220; Value_Code: 220R; Tolerance_%: 5; Power_W: 0.063; Value2: 0.063W; VDC_V: 50; TempCo: 200 ppm/C; SizeArea_mm2: 0.5; SizeX_mm: 1; SizeZ_mm: 0.6; EIA_Code: E24; U/M: EA; AEC Category: Q200
signal-integrity model Resistor
simulation model Resistor
footprint 0402
footprint 0402M
footprint 0402L
footprint 0402S
pins: 1, 2

## CRCW0402240RJNED
designator R?  ValueDisplayed: 240  (hidden comment: CRCW0402240RJNED)
RES, 240, 5%, 0.063 W, 0402; Manufacturer: Vishay-Dale; CompType: Resistor; Value: 240; Value_Code: 240R; Tolerance_%: 5; Power_W: 0.063; Value2: 0.063W; VDC_V: 50; TempCo: 200 ppm/C; SizeArea_mm2: 0.5; SizeX_mm: 1; SizeZ_mm: 0.6; EIA_Code: E24; U/M: EA; AEC Category: Q200
signal-integrity model Resistor
simulation model Resistor
footprint 0402
footprint 0402M
footprint 0402L
footprint 0402S
pins: 1, 2

## CRCW0402294RFKED
designator R?  ValueDisplayed: 294  (hidden comment: CRCW0402294RFKED)
RES, 294, 1%, 0.063 W, 0402; Manufacturer: Vishay-Dale; CompType: Resistor; Value: 294; Value_Code: 294R; Tolerance_%: 1; Power_W: 0.063; Value2: 0.063W; VDC_V: 50; TempCo: 100 ppm/C; SizeArea_mm2: 0.5; SizeZ_mm: 0.6; EIA_Code: E96; U/M: EA; AEC Category: Q200
signal-integrity model Resistor
simulation model Resistor
footprint 0402
footprint 0402M
footprint 0402L
footprint 0402S
pins: 1, 2

## CRCW0603100KFKEA
designator R?  ValueDisplayed: 100k  (hidden comment: CRCW0603100KFKEA)
RES, 100 k, 1%, 0.1 W, 0603; Manufacturer: Vishay-Dale; CompType: Resistor; Value: 100k; Res_ohm: 100000; Tolerance_%: 1; Power_W: 0.1; Value2: 0.1W; VDC_V: 75; TempCo: 100 ppm/C; SizeArea_mm2: 1.28; SizeX_mm: 1.6; SizeY_mm: 0.8; EIA_Code: E96; U/M: EA; AEC Category: Q200
signal-integrity model Resistor
simulation model Resistor
footprint 0603
footprint 0603M
footprint 0603L
footprint 0603_HV
footprint 0603S
pins: 1, 2

## CRCW0603100KJNEA
designator R?  ValueDisplayed: 100k  (hidden comment: CRCW0603100KJNEA)
RES, 100 k, 5%, 0.1 W, 0603; Manufacturer: Vishay-Dale; CompType: Resistor; Tolerance_%: 5; VDC_V: 75; Power_W: 0.1; Res_ohm: 100000; Value: 100k; U/M: EA; Value2: 0.1W; EIA_Code: E24; TempCo: 200 ppm/C; SizeArea_mm2: 1.28; SizeX_mm: 1.6; SizeY_mm: 0.8; SizeZ_mm: 1; AEC Category: Q200
signal-integrity model Resistor
simulation model Resistor
footprint 0603
footprint 0603M
footprint 0603L
footprint 0603_HV
footprint 0603S
pins: 1, 2

## CRCW0603100RFKEA
designator R?  ValueDisplayed: 100  (hidden comment: CRCW0603100RFKEA)
RES, 100, 1%, 0.1 W, 0603; Manufacturer: Vishay-Dale; CompType: Resistor; Tolerance_%: 1; VDC_V: 75; Power_W: 0.1; Value: 100; U/M: EA; Value_Code: 100R; Value2: 0.1W; EIA_Code: E96; TempCo: 100 ppm/C; SizeArea_mm2: 1.28; SizeX_mm: 1.6; SizeY_mm: 0.8; AEC Category: Q200
signal-integrity model Resistor
simulation model Resistor
footprint 0603
footprint 0603M
footprint 0603L
footprint 0603_HV
footprint 0603S
pins: 1, 2

## CRCW0603182KFKEA
designator R?  ValueDisplayed: 182k  (hidden comment: CRCW0603182KFKEA)
RES, 182 k, 1%, 0.1 W, 0603; Manufacturer: Vishay-Dale; CompType: Resistor; Value: 182k; Res_ohm: 182000; Tolerance_%: 1; Power_W: 0.1; Value2: 0.1W; VDC_V: 75; TempCo: 100 ppm/C; SizeArea_mm2: 1.28; SizeX_mm: 1.6; SizeY_mm: 0.8; EIA_Code: E96; U/M: EA; AEC Category: Q200
signal-integrity model Resistor
simulation model Resistor
footprint 0603
footprint 0603M
footprint 0603L
footprint 0603_HV
footprint 0603S
pins: 1, 2

## CRCW0603750RFKEA
designator R?  ValueDisplayed: 750  (hidden comment: CRCW0603750RFKEA)
RES, 750, 1%, 0.1 W, 0603; Manufacturer: Vishay-Dale; CompType: Resistor; Value: 750; Value_Code: 750R; Tolerance_%: 1; Power_W: 0.1; Value2: 0.1W; VDC_V: 75; TempCo: 100 ppm/C; SizeArea_mm2: 1.28; SizeX_mm: 1.6; SizeY_mm: 0.8; EIA_Code: E96; U/M: EA; AEC Category: Q200
signal-integrity model Resistor
simulation model Resistor
footprint 0603
footprint 0603M
footprint 0603L
footprint 0603_HV
footprint 0603S
pins: 1, 2

## CRCW04020000Z0ED
designator R?  ValueDisplayed: 0  (hidden comment: CRCW04020000Z0ED)
RES, 0, 5%, 0.063 W, 0402; Manufacturer: Vishay-Dale; CompType: Resistor; Value: 0; Value_Code: 0000; Tolerance_%: 5; Power_W: 0.063; Value2: 0.063W; VDC_V: 50; TempCo: 200 ppm/C; SizeArea_mm2: 0.5; SizeX_mm: 1; SizeZ_mm: 0.6; EIA_Code: E24; U/M: EA; AEC Category: Q200
signal-integrity model Resistor
simulation model Resistor
footprint 0402
footprint 0402M
footprint 0402L
footprint 0402S
pins: 1, 2

## CRCW06030000Z0EA
designator R?  ValueDisplayed: 0  (hidden comment: CRCW06030000Z0EA)
RES, 0, 5%, 0.1 W, 0603; Manufacturer: Vishay-Dale; CompType: Resistor; Tolerance_%: 5; VDC_V: 75; Power_W: 0.1; Value: 0; U/M: EA; Value_Code: 0000; Value2: 0.1W; EIA_Code: E24; TempCo: 200 ppm/C; SizeArea_mm2: 1.28; SizeX_mm: 1.6; SizeY_mm: 0.8; SizeZ_mm: 1; AEC Category: Q200
signal-integrity model Resistor
simulation model Resistor
footprint 0603
footprint 0603M
footprint 0603L
footprint 0603_HV
footprint 0603S
pins: 1, 2

## CSD15571Q2
designator Q?
MOSFET, N-CH, 20 V, 10 A, DQK0006C (WSON-6); Manufacturer: Texas Instruments; Alternate Manufacturer: None; U/M: EA; ChType: N; Value: 20V; VdsMax_V: 20; Value1: 19.2 ohm; Rdson45_ohm: 19.2; Value2: 2.5 nC; QgTyp_nC: 2.5; IdsMax_A: 10; SizeAreaWB_mm2: 9; SizeArea_mm2: 4; SizeX_mm: 2; SizeZ_mm: 0.8; AEC Category: Q101
footprint DQK0006C
pins: 1 D, 2 D, 3 G, 4 S, 5 D, 6 D, 7 S, 8 D

## CVHD-950-100.000
designator Y?  Frequency: 100 MHz  (hidden comment: CVHD-950-100.000)
VCXO, 100 MHz, 3.3V, SMD; Manufacturer: Crystek Corporation; SymbolCreator: a0412235; CompType: Oscillator; U/M: EA; TaMin_C: 0; TaMax_C: 70; Frequency Stability: ±20ppm
footprint OSC_CVHD-950-4
footprint OSC_CVHD-950-4_ExtPads
pins: 1 Vcont, 2 GND (power), 3 OUT, 4 Vcc (power)

## DS90LV028AQMA
designator U?
Automotive LVDS Dual Differential Line Receiver, 8-pin Narrow SOIC; Manufacturer: Texas Instruments; PackageTopMarking: NSZXTT*90LV0*28AQM; PowerWise: N; CompType: Interface IC
footprint M08A_N (SOIC, 8-Leads, Body 4.9x3.9mm, Pitch 1.27mm, IPC Medium Density)
footprint M08A_L (SOIC, 8-Leads, Body 4.9x3.9mm, Pitch 1.27mm, IPC High Density)
footprint M08A_M (SOIC, 8-Leads, Body 4.9x3.9mm, Pitch 1.27mm, IPC Low Density)
pins: 1 RIN1- (in), 2 RIN1+ (in), 3 RIN2+ (in), 4 RIN2- (in), 5 GND (power), 6 ROUT2 (out), 7 ROUT1 (out), 8 VCC (power)

## ERJ-1GN0R00C
designator R?  ValueDisplayed: 0  (hidden comment: ERJ-1GN0R00C)
RES, 0, 5%, 0.05 W, AEC-Q200 Grade 0, 0201; Manufacturer: Panasonic; CompType: Resistor; Tolerance_%: 5; Power_W: 0.05; Value: 0; U/M: EA; Value_Code: 0000; Value2: 0.05W; EIA_Code: E24; TempCo: ppm/C; SizeArea_mm2: 0.18; SizeX_mm: 0.6; SizeY_mm: 0.3; SizeZ_mm: 0.26; AEC Category: Q200; AEC Qualified: Y
signal-integrity model Resistor
simulation model Resistor
footprint 0201
footprint 0201M
footprint 0201L
footprint 0201_Silk
pins: 1, 2

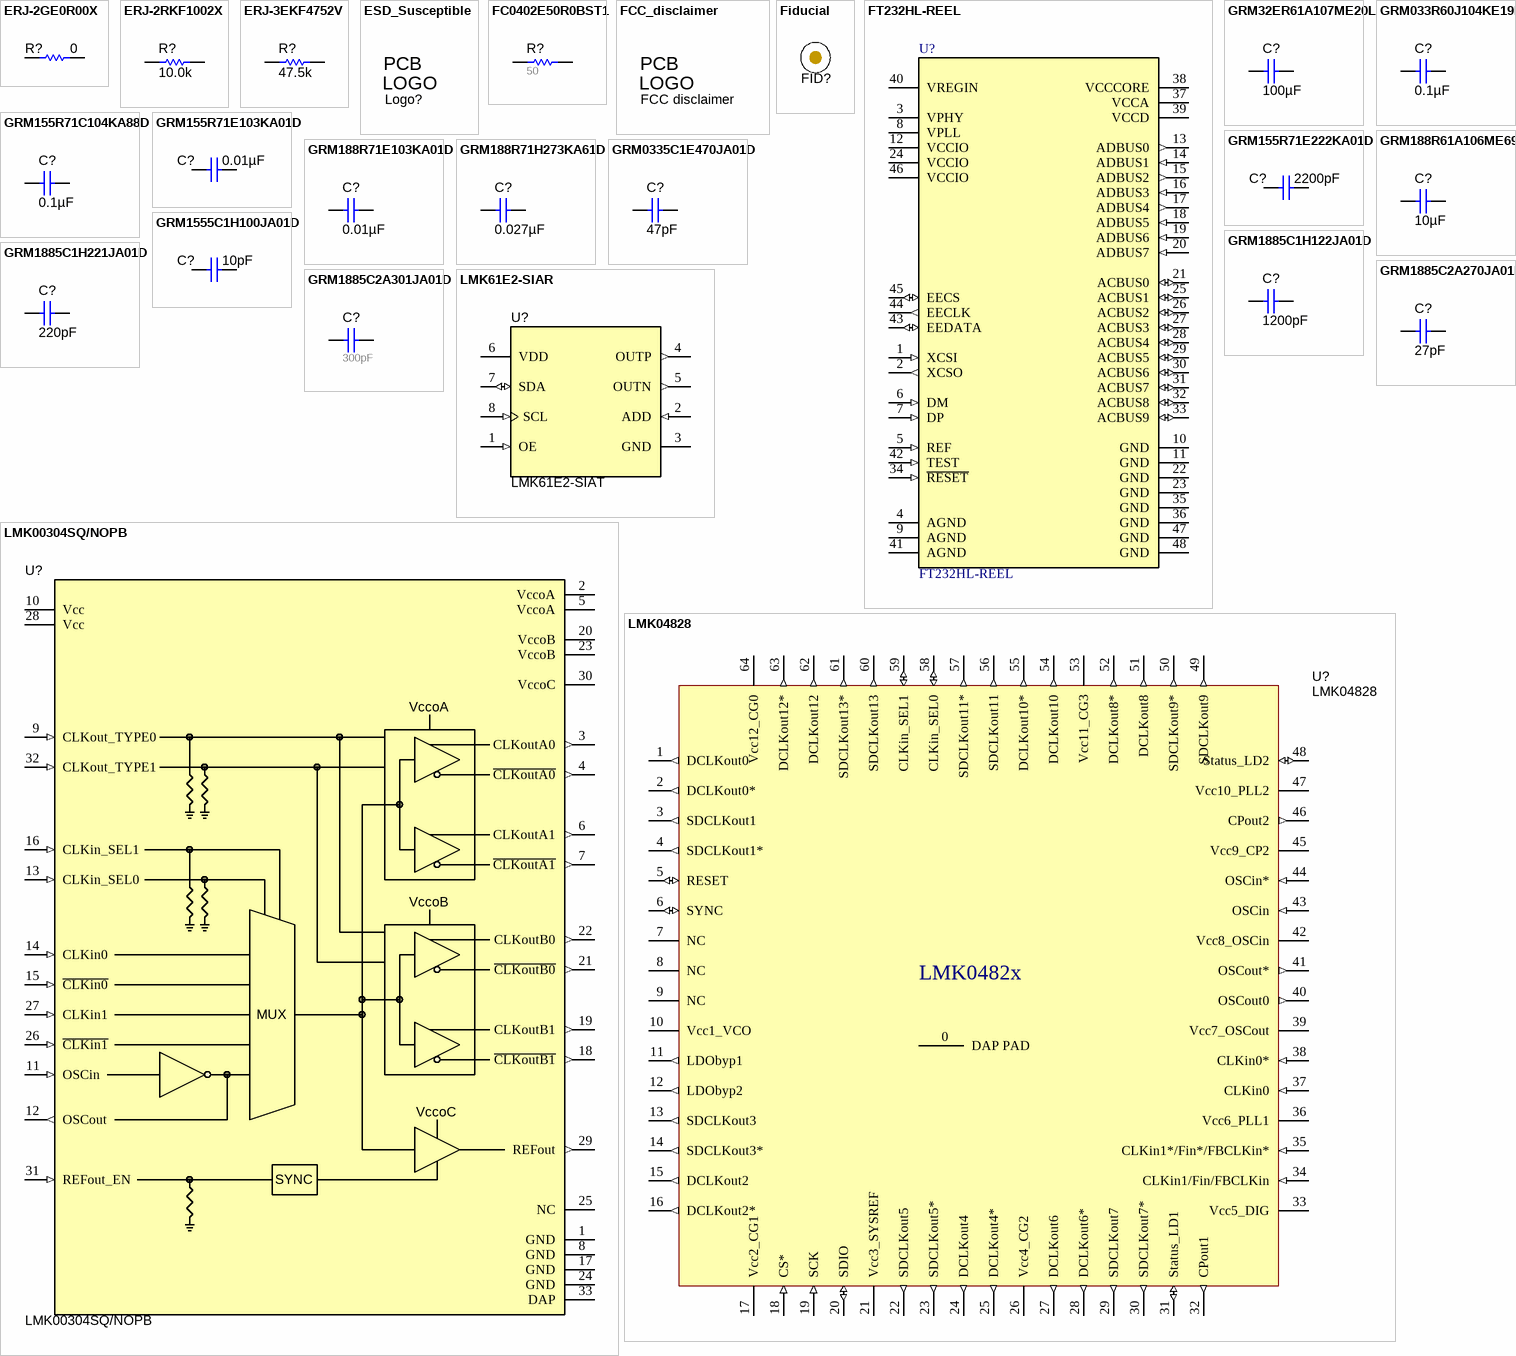
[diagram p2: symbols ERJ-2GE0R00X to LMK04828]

## ERJ-2GE0R00X
designator R?  ValueDisplayed: 0  (hidden comment: ERJ-2GE0R00X)
RES, 0, 5%, 0.063 W, 0402; Manufacturer: Panasonic; CompType: Resistor; Value: 0; Value_Code: 0000; Tolerance_%: 5; Power_W: 0.063; Value2: 0.063W; VDC_V: 50; TempCo: 600 ppm/C; SizeArea_mm2: 0.5; SizeX_mm: 1; SizeZ_mm: 0.6; EIA_Code: E24; U/M: EA; AEC Category: Q200
signal-integrity model Resistor
simulation model Resistor
footprint 0402
footprint 0402M
footprint 0402L
footprint 0402S
pins: 1, 2

## ERJ-2RKF1002X
designator R?  ValueDisplayed: 10.0k  (hidden comment: ERJ-2RKF1002X)
RES, 10.0 k, 1%, 0.1 W, 0402; Manufacturer: Panasonic; CompType: Resistor; Value: 10.0k; Res_ohm: 10000; Value_Code: 10k0; Tolerance_%: 1; Power_W: 0.1; Value2: 0.1W; VDC_V: 50; TempCo: 100 ppm/C; SizeArea_mm2: 0.5; SizeZ_mm: 0.6; EIA_Code: E96; U/M: EA; AEC Category: Q200
signal-integrity model Resistor
simulation model Resistor
footprint 0402
footprint 0402M
footprint 0402L
footprint 0402S
pins: 1, 2

## ERJ-3EKF4752V
designator R?  ValueDisplayed: 47.5k  (hidden comment: ERJ-3EKF4752V)
RES, 47.5 k, 1%, 0.1 W, AEC-Q200 Grade 0, 0603; Manufacturer: Panasonic; CompType: Resistor; Value: 47.5k; Res_ohm: 47500; Value_Code: 47k5; Tolerance_%: 1; Power_W: 0.1; Value2: 0.1W; VDC_V: 50; TempCo: 100 ppm/C; SizeArea_mm2: 1.28; SizeX_mm: 1.6; SizeY_mm: 0.8; EIA_Code: E96; U/M: EA; AEC Category: Q200; AEC Qualified: Y; AEC Grade: 0
signal-integrity model Resistor
simulation model Resistor
footprint 0603
footprint 0603M
footprint 0603L
footprint 0603_HV
footprint 0603S
pins: 1, 2

## ESD_Susceptible
designator Logo?, comment ESD Susceptible  (value not drawn)  (no BOM)
ESD Susceptible Symbol; SymbolCreator: a0412235
footprint ESD_Overlay_SMALL
footprint ESD_Overlay_Medium
footprint ESD_Overlay_Small

## FC0402E50R0BST1
designator R?  ValueDisplayed: 50  (hidden comment: FC0402E50R0BST1)
RES, 50, 0.1%, 0.05 W, 0402; Manufacturer: Vishay-Dale; CompType: Resistor; Value: 50; Value_Code: 50R0; Tolerance_%: 0.1; Power_W: 0.05; Value2: 0.05W; TempCo: 25 ppm/C; U/M: EA; SizeArea_mm2: 0.5; SizeX_mm: 1; SizeZ_mm: 0.6; AEC Category: Q200; AEC Qualified: N
signal-integrity model Resistor
simulation model Resistor
footprint 0402
footprint 0402M
footprint 0402L
footprint 0402S
pins: 1, 2

## FCC_disclaimer
designator Logo?, comment FCC disclaimer  (no BOM)
FCC_disclaimer; SymbolCreator: codlsc
footprint FCC_disclaimer
footprint FCC_disclaimer_stacked

## Fiducial
designator FID?  (value not drawn)
Fiducial mark.  There is nothing to buy or mount.; SymbolCreator: codlsc
footprint Fiducial10-30
footprint Fiducial10-20
footprint Fiducial15-30
footprint Fiducial20-40
footprint Fiducial6.4-20

## FT232HL-REEL
designator U?
Single Channel Hi-Speed USB to Multipurpose UART/FIFO IC, LQFP-48; Manufacturer: FTDI; SymbolCreator: Altium
footprint LQFP-48_N
footprint LQFP-48_L
footprint LQFP-48_M
pins: 1 XCSI (in), 2 XCSO (out), 3 VPHY (power), 4 AGND (power), 5 REF (in), 6 DM (in), 7 DP (in), 8 VPLL (power), 9 AGND (power), 10 GND (power), 11 GND (power), 12 VCCIO (power), 13 ADBUS0 (out), 14 ADBUS1 (in), 15 ADBUS2 (out), 16 ADBUS3 (in), 17 ADBUS4 (out), 18 ADBUS5 (in), 19 ADBUS6 (in), 20 ADBUS7 (in), 21 ACBUS0 (io), 22 GND (power), 23 GND (power), 24 VCCIO (power), 25 ACBUS1 (io), 26 ACBUS2 (io), 27 ACBUS3 (io), 28 ACBUS4 (io), 29 ACBUS5 (io), 30 ACBUS6 (io), 31 ACBUS7 (io), 32 ACBUS8 (io), 33 ACBUS9 (io), 34 ~{RESET} (in), 35 GND (power), 36 GND (power), 37 VCCA (power), 38 VCCCORE (power), 39 VCCD (power), 40 VREGIN (power), 41 AGND (power), 42 TEST (in), 43 EEDATA (io), 44 EECLK (out), 45 EECS (io), 46 VCCIO (power), 47 GND (power), 48 GND (power)

## GRM32ER61A107ME20L
designator C?  ValueDisplayed: 100µF  (hidden comment: GRM32ER61A107ME20L)
CAP, CERM, 100 µF, 10 V, +/- 20%, X5R, 1210; Manufacturer: MuRata; Polarized: N; CompType: Capacitor; Value: 100uF; U/M: EA; Cap_F: 0.0001; Tolerance_%: 20; Value1: Unknown; VDC_V: 10; Value2: 10V; TaMin_C: -55; TaMax_C: 85; Cap_Case: 1210; SizeArea_mm2: 8; SizeAreaWB_mm2: 14.7; SizeX_mm: 3.2; SizeY_mm: 2.5; SizeZ_mm: 2.7; AEC Category: Q200
signal-integrity model Cap
simulation model Cap
footprint 1210_270
footprint 1210_270M
footprint 1210_270L
pins: 1, 2

## GRM033R60J104KE19D
designator C?  ValueDisplayed: 0.1µF  (hidden comment: GRM033R60J104KE19D)
CAP, CERM, 0.1 µF, 6.3 V, +/- 10%, X5R, 0201; Manufacturer: MuRata; Polarized: N; CompType: Capacitor; Value: 0.1uF; U/M: EA; Cap_F: 0.0000001; Tolerance_%: 10; Value1: Unknown; VDC_V: 6.3; Value2: 6.3V; TaMin_C: -55; TaMax_C: 85; Cap_Case: 0201; SizeArea_mm2: 0.18; SizeAreaWB_mm2: 2.08; SizeX_mm: 0.6; SizeY_mm: 0.3; SizeZ_mm: 0.33; AEC Category: Q200
signal-integrity model Cap
simulation model Cap
footprint 0201_033
footprint 0201_033M
footprint 0201_033L
pins: 1, 2

## GRM155R71C104KA88D
designator C?  ValueDisplayed: 0.1µF  (hidden comment: GRM155R71C104KA88D)
CAP, CERM, 0.1 µF, 16 V, +/- 10%, X7R, 0402; Manufacturer: MuRata; Polarized: N; CompType: Capacitor; Value: 0.1uF; U/M: EA; Cap_F: 0.0000001; Tolerance_%: 10; Value1: Unknown; VDC_V: 16; Value2: 16V; TaMin_C: -55; TaMax_C: 125; Cap_Case: 0402; SizeArea_mm2: 0.5; SizeAreaWB_mm2: 3; SizeX_mm: 1; SizeZ_mm: 0.6; AEC Category: Q200
signal-integrity model Cap
simulation model Cap
footprint 0402
footprint 0402M
footprint 0402L
footprint 0402S
pins: 1, 2

## GRM155R71E103KA01D
designator C?  ValueDisplayed: 0.01µF  (hidden comment: GRM155R71E103KA01D)
CAP, CERM, 0.01 µF, 25 V, +/- 10%, X7R, 0402; Manufacturer: MuRata; Polarized: N; CompType: Capacitor; Value: 0.01uF; U/M: EA; Cap_F: 0.00000001; Tolerance_%: 10; Value1: Unknown; VDC_V: 25; Value2: 25V; TaMin_C: -55; TaMax_C: 125; Cap_Case: 0402; SizeArea_mm2: 0.5; SizeAreaWB_mm2: 3; SizeX_mm: 1; SizeZ_mm: 0.6; AEC Category: Q200
signal-integrity model Cap
simulation model Cap
footprint 0402
footprint 0402M
footprint 0402L
footprint 0402S
pins: 1, 2

## GRM155R71E222KA01D
designator C?  ValueDisplayed: 2200pF  (hidden comment: GRM155R71E222KA01D)
CAP, CERM, 2200 pF, 25 V, +/- 10%, X7R, 0402; Manufacturer: MuRata; Polarized: N; CompType: Capacitor; Value: 2200pF; U/M: EA; Cap_F: 0.0000000022; Tolerance_%: 10; Value1: Unknown; VDC_V: 25; Value2: 25V; TaMin_C: -55; TaMax_C: 125; Cap_Case: 0402; SizeArea_mm2: 0.5; SizeAreaWB_mm2: 3; SizeX_mm: 1; SizeZ_mm: 0.6; AEC Category: Q200
signal-integrity model Cap
simulation model Cap
footprint 0402
footprint 0402M
footprint 0402L
footprint 0402S
pins: 1, 2

## GRM188R61A106ME69D
designator C?  ValueDisplayed: 10µF  (hidden comment: GRM188R61A106ME69D)
CAP, CERM, 10 µF, 10 V, +/- 20%, X5R, 0603; Manufacturer: MuRata; Polarized: N; CompType: Capacitor; Value: 10uF; U/M: EA; Cap_F: 0.00001; Tolerance_%: 20; Value1: Unknown; VDC_V: 10; Value2: 10V; TaMin_C: -55; TaMax_C: 85; Cap_Case: 0603; SizeArea_mm2: 1.28; SizeAreaWB_mm2: 4.68; SizeX_mm: 1.6; SizeY_mm: 0.8; SizeZ_mm: 1; AEC Category: Q200; Green_Lifecycle: Active; Green_REACh: Passed
signal-integrity model Cap
simulation model Cap
footprint 0603
footprint 0603M
footprint 0603L
footprint 0603_HV
footprint 0603S
pins: 1, 2

## GRM188R71E103KA01D
designator C?  ValueDisplayed: 0.01µF  (hidden comment: GRM188R71E103KA01D)
CAP, CERM, 0.01 µF, 25 V, +/- 10%, X7R, 0603; Manufacturer: MuRata; Polarized: N; CompType: Capacitor; Value: 0.01uF; U/M: EA; Cap_F: 0.00000001; Tolerance_%: 10; Value1: Unknown; VDC_V: 25; Value2: 25V; TaMin_C: -55; TaMax_C: 125; Cap_Case: 0603; SizeArea_mm2: 1.28; SizeAreaWB_mm2: 4.68; SizeX_mm: 1.6; SizeY_mm: 0.8; SizeZ_mm: 1; AEC Category: Q200
signal-integrity model Cap
simulation model Cap
footprint 0603
footprint 0603M
footprint 0603L
footprint 0603_HV
footprint 0603S
pins: 1, 2

## GRM188R71H273KA61D
designator C?  ValueDisplayed: 0.027µF  (hidden comment: GRM188R71H273KA61D)
CAP, CERM, 0.027 µF, 50 V, +/- 10%, X7R, 0603; Manufacturer: MuRata; Cap_Case: 0603; Polarized: N; TaMax_C: 125; TaMin_C: -55; Tolerance_%: 10; VDC_V: 50; Cap_F: 0.000000027; CompType: Capacitor; Value: 0.027uF; Value1: Unknown; Value2: 50V; U/M: EA; AEC Category: Q200; SizeArea_mm2: 1.28; SizeAreaWB_mm2: 4.68; SizeX_mm: 1.6; SizeY_mm: 0.8; SizeZ_mm: 1
signal-integrity model Cap
simulation model Cap
footprint 0603
footprint 0603M
footprint 0603L
footprint 0603_HV
footprint 0603S
pins: 1, 2

## GRM0335C1E470JA01D
designator C?  ValueDisplayed: 47pF  (hidden comment: GRM0335C1E470JA01D)
CAP, CERM, 47 pF, 25 V, +/- 5%, C0G/NP0, 0201; Manufacturer: MuRata; Polarized: N; CompType: Capacitor; Value: 47pF; U/M: EA; Cap_F: 0.000000000047; Tolerance_%: 5; Value1: Unknown; VDC_V: 25; Value2: 25V; TaMin_C: -55; TaMax_C: 125; Cap_Case: 0201; SizeArea_mm2: 0.18; SizeAreaWB_mm2: 2.08; SizeX_mm: 0.6; SizeY_mm: 0.3; SizeZ_mm: 0.33; AEC Category: Q200
signal-integrity model Cap
simulation model Cap
footprint 0201_033
footprint 0201_033M
footprint 0201_033L
pins: 1, 2

## GRM1555C1H100JA01D
designator C?  ValueDisplayed: 10pF  (hidden comment: GRM1555C1H100JA01D)
CAP, CERM, 10 pF, 50 V, +/- 5%, C0G/NP0, 0402; Manufacturer: MuRata; Polarized: N; CompType: Capacitor; Value: 10pF; U/M: EA; Cap_F: 0.00000000001; Tolerance_%: 5; Value1: Unknown; VDC_V: 50; Value2: 50V; TaMin_C: -55; TaMax_C: 125; Cap_Case: 0402; SizeArea_mm2: 0.5; SizeAreaWB_mm2: 3; SizeX_mm: 1; SizeZ_mm: 0.6; AEC Category: Q200
signal-integrity model Cap
simulation model Cap
footprint 0402
footprint 0402M
footprint 0402L
footprint 0402S
pins: 1, 2

## GRM1885C1H122JA01D
designator C?  ValueDisplayed: 1200pF  (hidden comment: GRM1885C1H122JA01D)
CAP, CERM, 1200 pF, 50 V, +/- 5%, C0G/NP0, 0603; Manufacturer: MuRata; Cap_Case: 0603; Polarized: N; TaMax_C: 125; TaMin_C: -55; Tolerance_%: 5; VDC_V: 50; Cap_F: 0.0000000012; CompType: Capacitor; Value: 1200pF; Value1: Unknown; Value2: 50V; U/M: EA; SizeArea_mm2: 1.28; SizeAreaWB_mm2: 4.68; SizeX_mm: 1.6; SizeY_mm: 0.8; SizeZ_mm: 1; AEC Category: Q200
signal-integrity model Cap
simulation model Cap
footprint 0603
footprint 0603M
footprint 0603L
footprint 0603_HV
footprint 0603S
pins: 1, 2

## GRM1885C1H221JA01D
designator C?  ValueDisplayed: 220pF  (hidden comment: GRM1885C1H221JA01D)
CAP, CERM, 220 pF, 50 V, +/- 5%, C0G/NP0, 0603; Manufacturer: MuRata; Cap_Case: 0603; Polarized: N; TaMax_C: 125; TaMin_C: -55; Tolerance_%: 5; VDC_V: 50; Cap_F: 0.00000000022; CompType: Capacitor; Value: 220pF; Value1: Unknown; Value2: 50V; U/M: EA; AEC Category: Q200; SizeArea_mm2: 1.28; SizeAreaWB_mm2: 4.68; SizeX_mm: 1.6; SizeY_mm: 0.8; SizeZ_mm: 1
signal-integrity model Cap
simulation model Cap
footprint 0603
footprint 0603M
footprint 0603L
footprint 0603_HV
footprint 0603S
pins: 1, 2

## GRM1885C2A270JA01D
designator C?  ValueDisplayed: 27pF  (hidden comment: GRM1885C2A270JA01D)
CAP, CERM, 27 pF, 100 V, +/- 5%, C0G/NP0, 0603; Manufacturer: MuRata; Polarized: N; CompType: Capacitor; Value: 27pF; U/M: EA; Cap_F: 0.000000000027; Tolerance_%: 5; Value1: Unknown; VDC_V: 100; Value2: 100V; TaMin_C: -55; TaMax_C: 125; Cap_Case: 0603; SizeArea_mm2: 1.28; SizeAreaWB_mm2: 4.68; SizeX_mm: 1.6; SizeY_mm: 0.8; SizeZ_mm: 1; AEC Category: Q200
signal-integrity model Cap
simulation model Cap
footprint 0603
footprint 0603M
footprint 0603L
footprint 0603_HV
footprint 0603S
pins: 1, 2

## GRM1885C2A301JA01D
designator C?  ValueDisplayed: 300pF  (hidden comment: GRM1885C2A301JA01D)
CAP, CERM, 300pF, 100V, +/-5%, C0G/NP0, 0603; Manufacturer: MuRata; Cap_Case: 0603; Polarized: N; TaMax_C: 125; TaMin_C: -55; Tolerance_%: 5; VDC_V: 100; Cap_F: 0.0000000003; CompType: Capacitor; Value1: Unknown; U/M: EA
signal-integrity model Cap
simulation model Cap
footprint 0603
footprint 0603M
footprint 0603L
footprint 0603_HV
footprint 0603S
pins: 1, 2

## LMK61E2-SIAR
designator U?, comment LMK61E2-SIAT
Ultra-Low Jitter Programmable Oscillator with Internal EEPROM, SIA0008B; Manufacturer: Texas Instruments; SymbolCreator: Altium; CompType: IC; U/M: EA
footprint SIA0008B
pins: 1 OE (in), 2 ADD (in), 3 GND (power), 4 OUTP (out), 5 OUTN (out), 6 VDD (power), 7 SDA (io), 8 SCL (in)

## LMK00304SQ/NOPB
designator U?
3.1-GHz Differential Clock Buffer/Level Translator, RTV0032A (WQFN-32); Manufacturer: Texas Instruments; SymbolCreator: a0411947; SizeArea_mm2: 25; SizeAreaWB_mm2: 49; SizeX_mm: 5; SizeZ_mm: 0.8; CompType: IC; U/M: EA
footprint RTV0032A
pins: 1 GND (power), 2 VccoA (power), 3 CLKoutA0 (out), 4 ~{CLKoutA0} (out), 5 VccoA (power), 6 CLKoutA1 (out), 7 ~{CLKoutA1} (out), 8 GND (power), 9 CLKout_TYPE0 (in), 10 Vcc (power), 11 OSCin (in), 12 OSCout (out), 13 CLKin_SEL0 (in), 14 CLKin0 (in), 15 ~{CLKin0} (in), 16 CLKin_SEL1 (in), 17 GND (power), 18 ~{CLKoutB1} (out), 19 CLKoutB1 (out), 20 VccoB (power), 21 ~{CLKoutB0} (out), 22 CLKoutB0 (out), 23 VccoB (power), 24 GND (power), 25 NC, 26 ~{CLKin1} (in), 27 CLKin1 (in), 28 Vcc (power), 29 REFout (out), 30 VccoC (power), 31 REFout_EN (in), 32 CLKout_TYPE1 (in), 33 DAP (power)
1 alternate drawing of the same symbol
